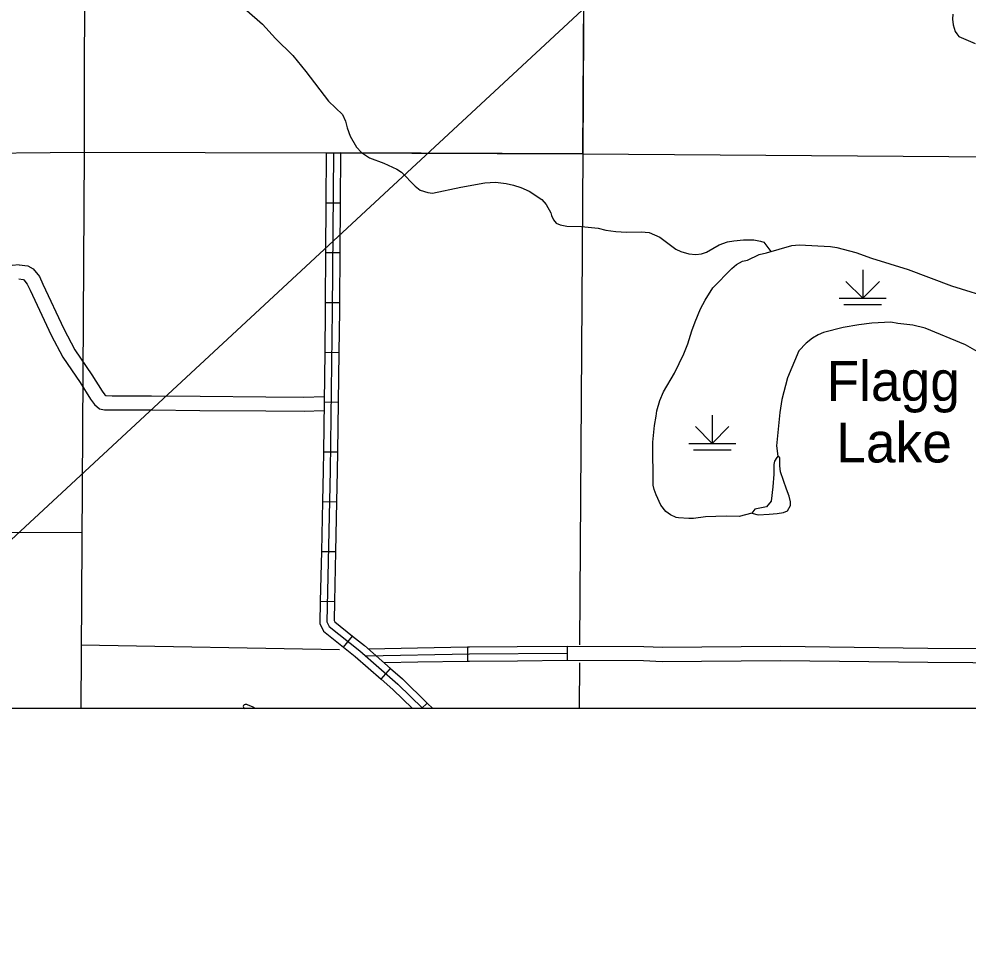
# Model space of a CAD drawing. Extents: x 1374139 to 1377472, y 1168351 to 1170484.
# Drawn here: x 1375369.3 to 1375570.5, y 1168603.5 to 1168800 of the extents above; entities that cross this region are included whole.
import ezdxf

# ---------------------------------------------------------------- set-up
doc = ezdxf.new("R2010")
doc.units = 0
for name, color, linetype in [('14', 7, 'Continuous'), ('26', 7, 'Continuous'), ('Default', 7, 'Continuous')]:
    doc.layers.add(name, color=color, linetype=linetype)

msp = doc.modelspace()

# ---------------------------------------------------------------- linework, layer by layer
at = {"layer": '14'}
msp.add_line((1375274.8, 1168603.49), (1375818.68, 1169108.27), dxfattribs=at)
at = {"layer": '26'}
msp.add_lwpolyline([(1375090, 1169579.43), (1376597.43, 1169579.43), (1376597.43, 1168653.79), (1375090, 1168653.79)], close=True, dxfattribs=at)
at = {"layer": 'Default'}
for p, q in [((1375488.68, 1168771.37), (1375490.09, 1168955.73)), ((1375434.37, 1168771.58), (1375437.37, 1168771.56)), ((1375434.37, 1168771.58), (1375488.68, 1168771.37)), ((1375434.3, 1168761.02), (1375437.3, 1168761)), ((1375434.23, 1168750.46), (1375437.23, 1168750.44)), ((1375547.99, 1168746.81), (1375547.99, 1168740.81)), ((1375547.99, 1168740.81), (1375544.45, 1168744.35)), ((1375547.99, 1168740.81), (1375551.52, 1168744.35)), ((1375434.16, 1168739.9), (1375437.16, 1168739.88)), ((1375542.99, 1168740.81), (1375552.99, 1168740.81)), ((1375543.99, 1168739.45), (1375551.99, 1168739.45)), ((1375434.03, 1168729.35), (1375437.03, 1168729.31)), ((1375433.9, 1168718.79), (1375436.9, 1168718.75)), ((1375516.13, 1168716.02), (1375516.13, 1168710.02)), ((1375516.13, 1168710.02), (1375512.6, 1168713.56)), ((1375516.13, 1168710.02), (1375519.67, 1168713.56)), ((1375511.13, 1168710.02), (1375521.13, 1168710.02)), ((1375433.76, 1168708.23), (1375436.76, 1168708.19)), ((1375512.13, 1168708.66), (1375520.13, 1168708.66)), ((1375433.57, 1168697.69), (1375436.56, 1168697.62)), ((1375433.33, 1168687.13), (1375436.33, 1168687.07)), ((1375433.1, 1168676.57), (1375436.1, 1168676.51)), ((1375438.04, 1168666.84), (1375439.91, 1168669.19)), ((1375464.25, 1168666.8), (1375464.31, 1168663.8)), ((1375485.39, 1168666.98), (1375485.41, 1168663.98)), ((1375446.02, 1168660.04), (1375448, 1168662.29)), ((1375454.55, 1168653.79), (1375455.72, 1168654.98))]:
    msp.add_line(p, q, dxfattribs=at)
for points in [[(1375383.98, 1169406.95), (1375383.06, 1168771.77)], [(1375554.39, 1168876.63), (1375542.31, 1168876.76), (1375542.16, 1168823.78), (1375489.02, 1168824.16), (1375488.68, 1168771.37), (1375437.37, 1168771.56)], [(1375417.53, 1168801.75), (1375420.84, 1168798.84), (1375423.64, 1168795.84), (1375427.27, 1168792.24), (1375430.01, 1168788.85), (1375434.85, 1168782.57), (1375437.78, 1168779.73), (1375438.42, 1168778.32), (1375438.81, 1168776.87), (1375439.46, 1168775.12), (1375440.75, 1168772.82), (1375441.86, 1168771.64), (1375443.51, 1168770.54), (1375446.58, 1168769.37), (1375449.33, 1168768.1), (1375450.29, 1168767.48), (1375453.22, 1168764.52), (1375454.28, 1168763.7), (1375455.88, 1168763.16), (1375456.86, 1168763.08), (1375462.85, 1168764.34), (1375467.97, 1168765.26), (1375470.22, 1168765.36), (1375472.45, 1168765.09), (1375474, 1168764.75), (1375475.61, 1168764.25), (1375477.33, 1168763.45), (1375480.04, 1168761.69), (1375480.94, 1168760.65), (1375481.93, 1168758.87), (1375482.06, 1168758.31), (1375482.5, 1168757.41), (1375483.04, 1168756.71), (1375483.89, 1168756.34), (1375485.3, 1168756.06), (1375488.46, 1168755.96), (1375491.93, 1168755.6), (1375493.6, 1168755.22), (1375495.67, 1168754.91), (1375497.99, 1168754.75), (1375501.05, 1168754.82), (1375502.73, 1168754.7), (1375505.02, 1168753.74), (1375508.4, 1168751.19), (1375509.49, 1168750.65), (1375511.15, 1168750.19), (1375512.67, 1168750.05), (1375513.85, 1168750.18), (1375514.9, 1168750.53), (1375517.6, 1168752.12), (1375519.38, 1168752.72)], [(1375567.12, 1168800.96), (1375567.01, 1168799.89), (1375567.16, 1168798.71), (1375567.61, 1168797.34), (1375567.93, 1168796.81), (1375568.34, 1168796.25), (1375571.84, 1168794.77)], [(1375338.65, 1168771.45), (1375354.31, 1168771.42), (1375383.06, 1168771.77), (1375434.37, 1168771.58)], [(1375383.06, 1168771.77), (1375382.41, 1168653.79)], [(1375434.37, 1168771.58), (1375434.3, 1168761.02)], [(1375435.87, 1168771.57), (1375435.64, 1168738.19), (1375435.21, 1168704.25), (1375434.51, 1168672.17), (1375434.97, 1168671.2), (1375441.48, 1168666.02), (1375449.5, 1168658.98), (1375454.79, 1168653.79)], [(1375437.37, 1168771.56), (1375437.3, 1168761)], [(1375488.68, 1168771.37), (1375487.99, 1168667.33)], [(1375488.68, 1168771.37), (1375595.34, 1168770.63), (1375618.13, 1168770.62)], [(1375434.3, 1168761.02), (1375434.23, 1168750.46)], [(1375437.3, 1168761), (1375437.23, 1168750.44)], [(1375524.5, 1168695.2), (1375521.86, 1168694.49), (1375519.04, 1168694.56), (1375514.72, 1168694.47), (1375512.17, 1168694.09), (1375511.17, 1168694.09), (1375509, 1168694.21), (1375508.48, 1168694.34), (1375507.25, 1168694.89), (1375506.27, 1168695.55), (1375505.22, 1168696.91), (1375504.24, 1168699.09), (1375503.81, 1168700.27), (1375503.63, 1168701.14), (1375503.56, 1168710.29), (1375503.89, 1168713.79), (1375504.28, 1168715.81), (1375504.38, 1168716.92), (1375505.04, 1168719.08), (1375505.82, 1168720.92), (1375508.12, 1168724.93), (1375510.12, 1168728.96), (1375510.94, 1168731.14), (1375511.77, 1168733.89), (1375512.48, 1168735.8), (1375513.62, 1168738.56), (1375514.59, 1168740.39), (1375516.27, 1168742.95), (1375520.24, 1168747.09), (1375521.26, 1168747.91), (1375522.55, 1168748.63), (1375523.58, 1168748.85), (1375526.07, 1168750.04), (1375527.62, 1168750.38), (1375532.96, 1168751.92), (1375534.54, 1168752.13), (1375541.15, 1168751.76), (1375542.51, 1168751.55), (1375546.56, 1168750.48), (1375549.87, 1168749.24), (1375557.59, 1168746.88), (1375566.8, 1168743.4), (1375575.93, 1168740.55)], [(1375519.38, 1168752.72), (1375520.7, 1168752.96), (1375522.71, 1168753.15), (1375524.95, 1168753.16), (1375526.36, 1168752.9), (1375527.07, 1168752.63), (1375528.55, 1168750.66)], [(1375434.23, 1168750.46), (1375434.16, 1168739.9)], [(1375437.23, 1168750.44), (1375437.16, 1168739.88)], [(1375369.31, 1168747.88), (1375367.81, 1168747.75)], [(1375369.31, 1168747.88), (1375371.17, 1168747.66), (1375372.27, 1168747), (1375373.59, 1168745.38), (1375374.34, 1168743.74), (1375378.81, 1168734.28), (1375381.14, 1168729.85), (1375384.72, 1168724.54), (1375386.89, 1168721.11), (1375387.47, 1168720.33), (1375387.7, 1168720.14), (1375387.74, 1168720.13), (1375389.01, 1168720.09), (1375397.37, 1168720.09), (1375407.63, 1168720.01), (1375421.57, 1168719.89), (1375429.64, 1168719.81), (1375433.91, 1168719.96)], [(1375369.27, 1168744.86), (1375370.18, 1168744.76), (1375370.27, 1168744.7), (1375371.02, 1168743.78), (1375371.62, 1168742.48), (1375376.13, 1168732.94), (1375378.56, 1168728.31), (1375382.21, 1168722.9), (1375384.42, 1168719.41), (1375385.26, 1168718.28), (1375386.31, 1168717.37), (1375387.38, 1168717.14), (1375388.97, 1168717.09), (1375397.36, 1168717.09), (1375407.6, 1168717.01), (1375421.54, 1168716.89), (1375429.68, 1168716.81), (1375433.87, 1168716.96)], [(1375434.16, 1168739.9), (1375434.14, 1168738.21), (1375434.03, 1168729.35)], [(1375437.16, 1168739.88), (1375437.14, 1168738.18), (1375437.03, 1168729.31)], [(1375585.2, 1168721.64), (1375580.1, 1168725.12), (1375577.38, 1168726.74), (1375572.23, 1168729.48), (1375569.75, 1168730.91), (1375561.24, 1168734.41), (1375558.61, 1168735.05), (1375555.4, 1168735.41), (1375553.97, 1168735.68), (1375549.91, 1168735.52), (1375547.18, 1168735.17), (1375543.86, 1168734.56), (1375539.7, 1168733.5), (1375538.56, 1168733.05), (1375537.33, 1168732.3), (1375536, 1168731.28), (1375534.5, 1168729.62), (1375532.08, 1168723.94), (1375530.84, 1168719.35), (1375530.41, 1168716.57), (1375529.72, 1168709.47), (1375530.04, 1168707.27)], [(1375434.03, 1168729.35), (1375433.9, 1168718.79)], [(1375437.03, 1168729.31), (1375436.9, 1168718.75)], [(1375433.9, 1168718.79), (1375433.76, 1168708.23)], [(1375436.9, 1168718.75), (1375436.76, 1168708.19)], [(1375433.76, 1168708.23), (1375433.71, 1168704.28), (1375433.57, 1168697.69)], [(1375436.76, 1168708.19), (1375436.71, 1168704.22), (1375436.56, 1168697.62)], [(1375530.04, 1168707.27), (1375529.78, 1168707.05), (1375529.33, 1168706.21), (1375529.18, 1168705.51), (1375529.17, 1168703.52), (1375528.98, 1168700.79), (1375528.62, 1168697.77), (1375527.64, 1168696.55), (1375525.16, 1168696.06), (1375524.5, 1168695.2), (1375525.87, 1168694.89), (1375528.16, 1168695.01), (1375529.9, 1168695.15), (1375531.24, 1168695.4), (1375532.03, 1168695.72), (1375532.68, 1168696.86), (1375532.7, 1168697.63), (1375532.45, 1168698.82), (1375531.83, 1168700.31)], [(1375531.83, 1168700.31), (1375530.6, 1168704), (1375530.43, 1168705.24), (1375530.45, 1168706.92), (1375530.04, 1168707.27)], [(1375433.57, 1168697.69), (1375433.33, 1168687.13)], [(1375436.56, 1168697.62), (1375436.33, 1168687.07)], [(1375309.16, 1168691.25), (1375382.61, 1168691.1)], [(1375433.33, 1168687.13), (1375433.1, 1168676.57)], [(1375436.33, 1168687.07), (1375436.1, 1168676.51)], [(1375433.1, 1168676.57), (1375433, 1168671.84), (1375433.77, 1168670.24), (1375438.04, 1168666.84)], [(1375436.1, 1168676.51), (1375436.02, 1168672.49), (1375436.18, 1168672.16), (1375439.91, 1168669.19)], [(1375439.91, 1168669.19), (1375442.44, 1168667.17), (1375448, 1168662.29)], [(1375437.17, 1168666.24), (1375382.48, 1168667.27)], [(1375438.04, 1168666.84), (1375440.52, 1168664.87), (1375446.02, 1168660.04)], [(1375485.4, 1168665.48), (1375464.73, 1168665.31), (1375442.73, 1168664.92)], [(1375453.7, 1168666.62), (1375443.28, 1168666.43)], [(1375464.25, 1168666.8), (1375453.7, 1168666.62)], [(1375474.83, 1168666.89), (1375464.71, 1168666.81), (1375464.25, 1168666.8)], [(1375485.39, 1168666.98), (1375474.83, 1168666.89)], [(1375580.83, 1168666.46), (1375561.8, 1168666.56), (1375530.57, 1168666.93), (1375505.58, 1168666.73), (1375501.61, 1168666.91), (1375485.39, 1168666.98)], [(1375453.75, 1168663.62), (1375446.63, 1168663.49)], [(1375464.31, 1168663.8), (1375453.75, 1168663.62)], [(1375474.85, 1168663.89), (1375464.74, 1168663.81), (1375464.31, 1168663.8)], [(1375485.41, 1168663.98), (1375474.85, 1168663.89)], [(1375580.84, 1168663.46), (1375561.77, 1168663.56), (1375530.57, 1168663.93), (1375505.52, 1168663.73), (1375501.54, 1168663.91), (1375485.41, 1168663.98)], [(1375487.98, 1168663.5), (1375487.96, 1168653.79)], [(1375448, 1168662.29), (1375450.52, 1168660.08), (1375455.72, 1168654.98)], [(1375446.02, 1168660.04), (1375448.48, 1168657.88), (1375452.65, 1168653.79)], [(1375417.85, 1168654.52), (1375417.55, 1168654.64), (1375417.21, 1168654.68), (1375416.99, 1168654.63), (1375416.83, 1168654.47), (1375416.79, 1168654.23), (1375416.9, 1168653.99), (1375417.09, 1168653.79)], [(1375419.42, 1168653.79), (1375419.38, 1168653.82), (1375418.91, 1168654.11), (1375418.42, 1168654.31), (1375417.85, 1168654.52)], [(1375455.72, 1168654.98), (1375456.93, 1168653.79)]]:
    msp.add_lwpolyline(points, dxfattribs=at)

# ---------------------------------------------------------------- texts
for s, p in [('Flagg', (1375540.33, 1168719.02)), ('Lake', (1375542.39, 1168705.97))]:
    msp.add_text(s, height=8.448, dxfattribs=at).set_placement(p)

doc.saveas('drawing.dxf')
